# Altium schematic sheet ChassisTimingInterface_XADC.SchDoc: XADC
size B; DocumentNumber: 5; Revision: C; SheetNumber: 10; SheetTotal: 12
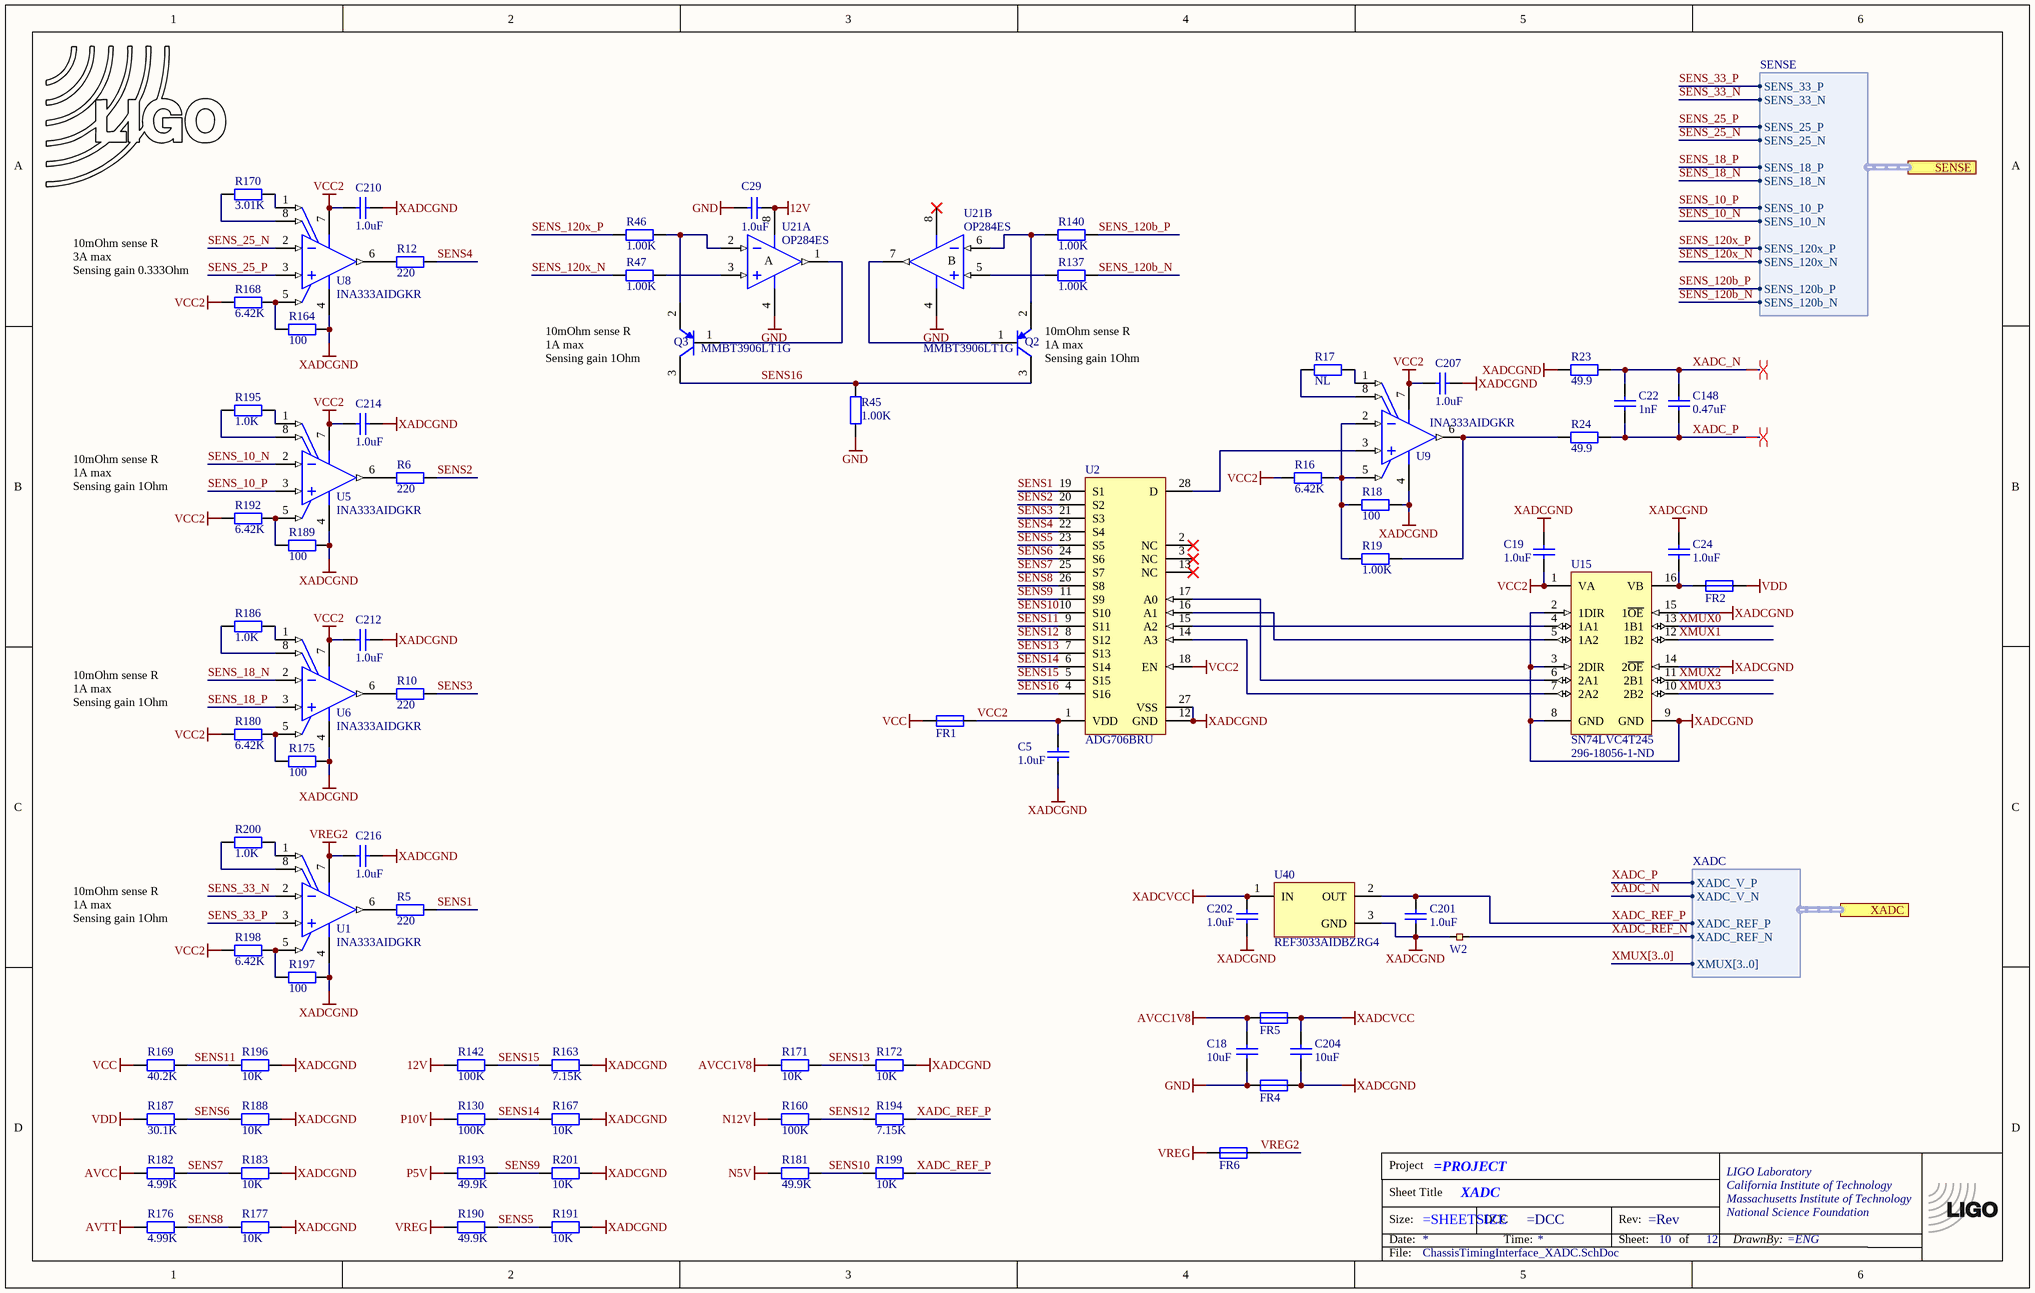
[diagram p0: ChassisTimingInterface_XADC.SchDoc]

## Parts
*  TitleBlock  (value not drawn)  (graphical)
C5  1.0uF  [CC1608-0603]
C18  10uF  [CC2013-0805]
C19  1.0uF  [CC1608-0603]
C22  1nF  [CC1005-0402]
C24  1.0uF  [CC1608-0603]
C29  1.0uF  [CC1608-0603]
C148  0.47uF  [CAPC0603X33X15NL03T05]
C201  1.0uF  [CC1608-0603]
C202  1.0uF  [CC1608-0603]
C204  10uF  [CC2013-0805]
C207  1.0uF  [CC1608-0603]
C210  1.0uF  [CC1608-0603]
C212  1.0uF  [CC1608-0603]
C214  1.0uF  [CC1608-0603]
C216  1.0uF  [CC1608-0603]
FR1  BLM31PG121  [CC3216-1206]  (value not drawn)
FR2  BLM31PG121  [CC3216-1206]  (value not drawn)
FR4  BLM31PG121  [CC3216-1206]  (value not drawn)
FR5  BLM31PG121  [CC3216-1206]  (value not drawn)
FR6  BLM31PG121  [CC3216-1206]  (value not drawn)
LOGO4  LIGO logo  [LIGO_LOGO]  (value not drawn)  (graphical)
Q2  MMBT3906LT1G  [ONSC-SOT-23-3-318-08_V]
Q3  MMBT3906LT1G  [ONSC-SOT-23-3-318-08_V]
R5  220  [CR1608-0603]
R6  220  [CR1608-0603]
R10  220  [CR1608-0603]
R12  220  [CR1608-0603]
R16  6.42K  [CR1608-0603]
R17  NL  [CR1608-0603]
R18  100  [CR1608-0603]
R19  value 1.00K  [CR1608-0603]  (hidden comment: 1.0k)
R23  49.9  [CR1608-0603]
R24  49.9  [CR1608-0603]
R45  value 1.00K  [CR1608-0603]  (hidden comment: 1.0k)
R46  value 1.00K  [CR1608-0603]  (hidden comment: 1.0k)
R47  value 1.00K  [CR1608-0603]  (hidden comment: 1.0k)
R130  100K  [CR1005-0402]
R137  value 1.00K  [CR1608-0603]  (hidden comment: 1.0k)
R140  value 1.00K  [CR1608-0603]  (hidden comment: 1.0k)
R142  100K  [CR1005-0402]
R160  100K  [CR1005-0402]
R163  7.15K  [CR1005-0402]
R164  100  [CR1608-0603]
R167  10K  [CR1005-0402]
R168  6.42K  [CR1608-0603]
R169  40.2K  [CR1608-0603]
R170  3.01K  [CR1608-0603]
R171  10K  [CR1005-0402]
R172  10K  [CR1005-0402]
R175  100  [CR1608-0603]
R176  4.99K  [CR1608-0603]
R177  10K  [CR1005-0402]
R180  6.42K  [CR1608-0603]
R181  49.9K  [CR1005-0402]
R182  4.99K  [CR1608-0603]
R183  10K  [CR1005-0402]
R186  1.0K  [CR1608-0603]
R187  30.1K  [CR1608-0603]
R188  10K  [CR1005-0402]
R189  100  [CR1608-0603]
R190  49.9K  [CR1005-0402]
R191  10K  [CR1005-0402]
R192  6.42K  [CR1608-0603]
R193  49.9K  [CR1005-0402]
R194  7.15K  [CR1005-0402]
R195  1.0K  [CR1608-0603]
R196  10K  [CR1005-0402]
R197  100  [CR1608-0603]
R198  6.42K  [CR1608-0603]
R199  10K  [CR1005-0402]
R200  1.0K  [CR1608-0603]
R201  10K  [CR1005-0402]
U1  INA333AIDGKR  [DGK0008A_N]
U2  ADG706BRU  [ADI-RU-28_M]
U5  INA333AIDGKR  [DGK0008A_N]
U6  INA333AIDGKR  [DGK0008A_N]
U8  INA333AIDGKR  [DGK0008A_N]
U9  INA333AIDGKR  [DGK0008A_N]
U15  SN74LVC4T245  Supplier Part Number 1: 296-18056-1-ND  [TSSOP16]
U21  OP284ES  [SO-8_N]  (parts A,B of 2)
U40  REF3033AIDBZRG4  [TI-DBZ3_N]
W2  Net tie  [NETTIE1_SMDTOP]  (value not drawn)  (net tie, no BOM)

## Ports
SENSE (harness SENSE), XADC (harness XADC)

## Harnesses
XADC: XADC_REF_P, XADC_V_N, XADC_V_P, XMUX[3..0], XADC_REF_N
SENSE: SENS_33_P, SENS_33_N, SENS_25_P, SENS_25_N, SENS_18_P, SENS_18_N, SENS_10_P, SENS_10_N, SENS_120x_P, SENS_120x_N, SENS_120b_P, SENS_120b_N

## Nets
12V: C29.1 R142.1 U21.8(V+)
AVCC: R182.1
AVCC1V8: C18.1 FR5.1 R171.1
AVTT: R176.1
GND: C18.2 C29.2 FR4.1 R45.2 U21.4(V-)
N5V: R181.1
N12V: R160.1
P5V: R193.1
P10V: R130.1
VCC: FR1.1 R169.1
VCC2: C5.1 C19.2 C207.1 C210.1 C212.1 C214.1 FR1.2 R16.1 R168.1 R180.1 R192.1 R198.1 U2.1(VDD) U2.18(EN) U5.7(V+) U6.7(V+) U8.7(V+) U9.7(V+) U15.1(VA)
VDD: FR2.2 R187.1
VREG: FR6.1 R190.1
VREG2: C216.1 FR6.2 U1.7(V+)
XADCGND: C5.2 C19.1 C24.1 C201.2 C202.2 C204.2 C207.2 C210.2 C212.2 C214.2 C216.2 FR4.2 R18.2 R23.1 R163.2 R164.2 R167.2 R172.2 R175.2 R177.2 R183.2 R188.2 R189.2 R191.2 R196.2 R197.2 R201.2 U1.4(V-) U2.12(GND) U2.27(VSS) U5.4(V-) U6.4(V-) U8.4(V-) U9.4(V-) U15.2(1DIR) U15.3(2DIR) U15.8(GND) U15.9(GND) U15.14(2~{OE}) U15.15(1~{OE}) U40.3(GND) W2.1
XADCVCC: C202.1 C204.1 FR5.2 U40.1(IN)
SENS1: R5.2 U2.19(S1)
SENS2: R6.2 U2.20(S2)
SENS3: R10.2 U2.21(S3)
SENS4: R12.2 U2.22(S4)
SENS5: R190.2 R191.1 U2.23(S5)
SENS6: R187.2 R188.1 U2.24(S6)
SENS7: R182.2 R183.1 U2.25(S7)
SENS8: R176.2 R177.1 U2.26(S8)
SENS9: R193.2 R201.1 U2.11(S9)
SENS10: R181.2 R199.1 U2.10(S10)
SENS11: R169.2 R196.1 U2.9(S11)
SENS12: R160.2 R194.1 U2.8(S12)
SENS13: R171.2 R172.1 U2.7(S13)
SENS14: R130.2 R167.1 U2.6(S14)
SENS15: R142.2 R163.1 U2.5(S15)
SENS16: Q2.3(C) Q3.3(C) R45.1 U2.4(S16)
SENS_10_N: U5.2(VIN-) ; port SENSE.SENS_10_N
SENS_10_P: U5.3(VIN+) ; port SENSE.SENS_10_P
SENS_18_N: U6.2(VIN-) ; port SENSE.SENS_18_N
SENS_18_P: U6.3(VIN+) ; port SENSE.SENS_18_P
SENS_25_N: U8.2(VIN-) ; port SENSE.SENS_25_N
SENS_25_P: U8.3(VIN+) ; port SENSE.SENS_25_P
SENS_33_N: U1.2(VIN-) ; port SENSE.SENS_33_N
SENS_33_P: U1.3(VIN+) ; port SENSE.SENS_33_P
SENS_120b_N: R137.1 ; port SENSE.SENS_120b_N
SENS_120b_P: R140.1 ; port SENSE.SENS_120b_P
SENS_120x_N: R47.2 ; port SENSE.SENS_120x_N
SENS_120x_P: R46.2 ; port SENSE.SENS_120x_P
XADC_N: C22.2 C148.2 R23.2 ; port XADC.XADC_V_N
XADC_P: C22.1 C148.1 R24.2 ; port XADC.XADC_V_P
XADC_REF_N: W2.2 ; port XADC.XADC_REF_N
XADC_REF_P: C201.1 R194.2 R199.2 U40.2(OUT) ; port XADC.XADC_REF_P
XMUX0: U15.13(1B1)
XMUX1: U15.12(1B2)
XMUX2: U15.11(2B1)
XMUX3: U15.10(2B2)
NetC24_2: C24.2 FR2.1 U15.16(VB)
NetQ2_1: Q2.1(B) U21.7(OUT)
NetQ2_2: Q2.2(E) R140.2 U21.6(IN-)
NetQ3_1: Q3.1(B) U21.1(OUT)
NetQ3_2: Q3.2(E) R46.1 U21.2(IN-)
NetR5_1: R5.1 U1.6(VOUT)
NetR6_1: R6.1 U5.6(VOUT)
NetR10_1: R10.1 U6.6(VOUT)
NetR12_1: R12.1 U8.6(VOUT)
NetR16_2: R16.2 R18.1 R19.1 U9.2(VIN-) U9.5(REF)
NetR17_1: R17.1 U9.8(RG)
NetR17_2: R17.2 U9.1(RG)
NetR19_2: R19.2 R24.1 U9.6(VOUT)
NetR47_1: R47.1 U21.3(IN+)
NetR137_2: R137.2 U21.5(IN+)
NetR164_1: R164.1 R168.2 U8.5(REF)
NetR170_1: R170.1 U8.8(RG)
NetR170_2: R170.2 U8.1(RG)
NetR175_1: R175.1 R180.2 U6.5(REF)
NetR186_1: R186.1 U6.8(RG)
NetR186_2: R186.2 U6.1(RG)
NetR189_1: R189.1 R192.2 U5.5(REF)
NetR195_1: R195.1 U5.8(RG)
NetR195_2: R195.2 U5.1(RG)
NetR197_1: R197.1 R198.2 U1.5(REF)
NetR200_1: R200.1 U1.8(RG)
NetR200_2: R200.2 U1.1(RG)
NetU2_14: U2.14(A3) U15.7(2A2)
NetU2_15: U2.15(A2) U15.4(1A1)
NetU2_16: U2.16(A1) U15.5(1A2)
NetU2_17: U2.17(A0) U15.6(2A1)
NetU2_28: U2.28(D) U9.3(VIN+)

Not connected (* = marked no-connect by the designer): U2 2(NC)* 3(NC)* 13(NC)*

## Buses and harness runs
bus XMUX[3..0]

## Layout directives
differential pair: XADC_N, XADC_P

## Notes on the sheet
- 10mOhm sense R
  3A max
  Sensing gain 0.333Ohm
- (near Q3) 10mOhm sense R
  1A max
  Sensing gain 1Ohm
- (near Q2) 10mOhm sense R
  1A max
  Sensing gain 1Ohm
- 10mOhm sense R
  1A max
  Sensing gain 1Ohm

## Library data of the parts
C5 C19 C24 C29 C201 C202 C207 C210 C212 C214 C216 = ChipCap: C0603 1.0uF; Part Number: 1276-1184-1-ND; Tolerance: 10%
C18 C204 = ChipCap: C0805 10uF; Part Number: 1276-6454-1-ND; Tolerance: 10%
C22 = ChipCap: C0402 1.0nF; Part Number: 1292-1246-1-ND; Tolerance: 10%
C148 = CMP-2010-00306-1: C0201 0.47uF; Part Number: 1276-6445-1-ND; Tolerance: 10%
FR1 FR2 FR4-FR6 = BLM31PG121SN1: ferrite bead, 120Ohm at 100MHz, 1206; Part Number: 490-1056-1-ND
LOGO4 = LIGO_logo
Q2 Q3 = CMP-1048-00670-1: General Purpose Transistor, PNP Silicon, 3-Pin SOT-23, Pb-Free, Tape and Reel; Part Number: MMBT3906LT1GOSCT-ND
R5 R6 R10 R12 = ChipRes1: R0603 220; Part Number: RR08P220DCT-ND; Tolerance: 0.1%
R16 R168 R180 R192 R198 = ChipRes1: R0603 6.42k; Part Number: RR08P6.49KDCT-ND; Tolerance: 0.1%
R17 = ChipRes1: Resistor, surface mount; Tolerance: 0.1%
R18 R164 R175 R189 R197 = ChipRes1: R0603 100; Part Number: RR08P100DCT-ND; Tolerance: 0.1%
R19 R45-R47 R137 R140 = ChipRes1: R0603 1.0k; Part Number: RR08P1.0KDCT-ND; Tolerance: 1%
R23 R24 = ChipRes1: R0603 49.9; Part Number: RR08Q49.9DCT-ND; Tolerance: 0.1%
R130 R142 R160 = ChipRes1: R0402 100k; Part Number: RR05P100KDCT-ND; Tolerance: 0.1%
R163 R194 = ChipRes1: R0402 7.15k; Part Number: YAG1478CT-ND; Tolerance: 0.1%
R167 R171 R172 R177 R183 R188 R191 R196 R199 R201 = ChipRes1: R0402 10k; Part Number: RR05P10.0KDCT-ND; Tolerance: 0.1%
R169 = ChipRes1: R0603 40.2k; Part Number: RR08P40.2KDCT-ND; Tolerance: 0.1%
R170 = ChipRes1: R0603 3.01k; Part Number: RR08P3.01KDCT-ND; Tolerance: 0.1%
R176 R182 = ChipRes1: R0603 4.99k; Part Number: RR08P4.99KDCT-ND; Tolerance: 0.1%
R181 R190 R193 = ChipRes1: R0402 49.9k; Part Number: RR05P49.9KDCT-ND; Tolerance: 0.1%
R186 R195 R200 = ChipRes1: R0603 1.0k; Part Number: RR08P1.0KDCT-ND; Tolerance: 0.1%
R187 = ChipRes1: R0603 30.1k; Part Number: RR08P30.1KDCT-ND; Tolerance: 0.1%
U1 U5 U6 U8 U9 = CMP-0944-00088-2: Low Power, Precision Instrumentation Amplifier, -40 to 125 degC, 8-pin SOP (DGK8), Green (RoHS & no Sb/Br); Part Number: 296-23564-1-ND
U2 = CMP-0798-00217-1: 1.8 to 5.5 V / 2.5 V, CMOS Low-Voltage 2.5 Ohm, 16-Channel Multiplexer, -40 to 85 degC, 28-pin SOP (RU-28), Tube; Part Number: ADG706BRUZ-REEL7CT-ND
U15 = SN74LVC4T245: Quad-Bit Dual Supply Transceiver
U21 = OP284ES: Precision Rail-to-Rail Input and Output Operational Amplifier; Part Number: OP284ESZ-REEL7TR-ND
U40 = CMP-0367-00169-1: 3.3 V, 50 ppm / degC, 50 uA Series (Bandgap) Voltage Reference, -40 to 125 degC, 3-pin SOT-23 (DBZ), Green (RoHS & no Sb/Br); Part Number: 296-52689-1-ND
W2 = NetTie1_small: Tie two nets together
